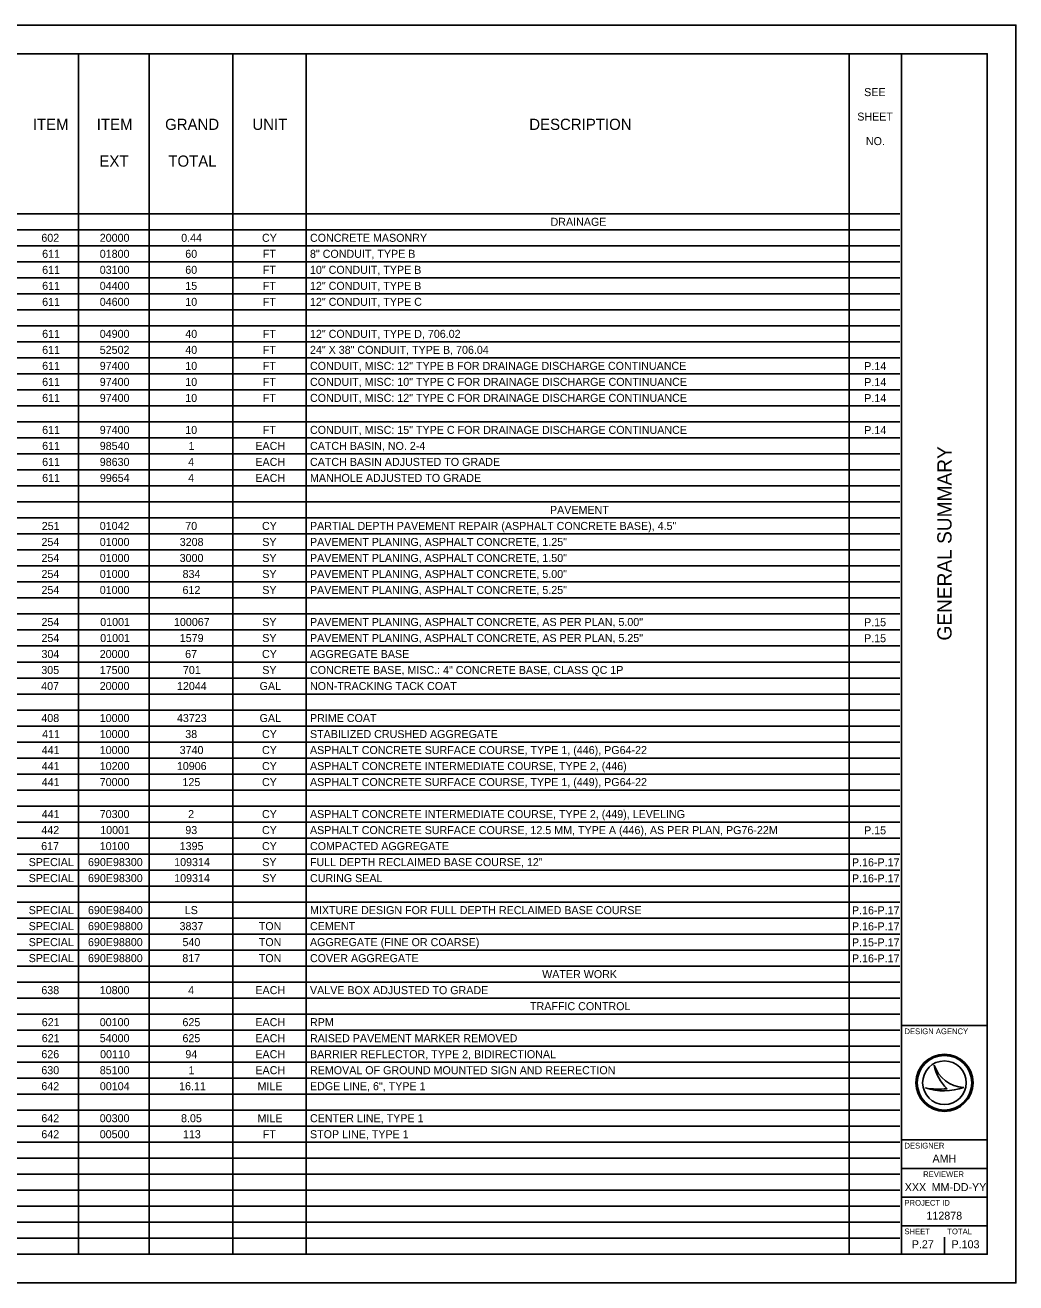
# Model space of a CAD drawing. Extents: x 0 to 34, y 0 to 22.
# Drawn here: x 16.66 to 34, y 0 to 22 of the extents above; entities that cross this region are included whole.
import ezdxf

# ---------------------------------------------------------------- set-up
doc = ezdxf.new("R2010")
doc.units = 0
for name, color, linetype in [('SH_Border', 7, 'Continuous'), ('SH_Cut_Line', 7, 'Continuous'), ('SH_Data', 7, 'Continuous'), ('SH_Text', 7, 'Continuous')]:
    doc.layers.add(name, color=color, linetype=linetype)

msp = doc.modelspace()

# ---------------------------------------------------------------- linework, layer by layer
at = {"layer": 'SH_Border'}
for p, q in [((32, 0.5), (32, 21.5)), ((32, 4.5), (33.5, 4.5)), ((32, 2.5), (33.5, 2.5)), ((32, 2), (33.5, 2)), ((32, 1.5), (33.5, 1.5)), ((32, 1), (33.5, 1))]:
    msp.add_line(p, q, dxfattribs=at)
msp.add_lwpolyline([(1.5, 21.5), (33.5, 21.5), (33.5, 0.5), (1.5, 0.5)], close=True, dxfattribs=at)
at = {"layer": 'SH_Cut_Line'}
msp.add_lwpolyline([(0, 0), (34, 0), (34, 22), (0, 22)], close=True, dxfattribs=at)
at = {"layer": 'SH_Data'}
for p, q in [((32.567, 3.81), (32.567, 3.81)), ((32.417, 3.41), (32.417, 3.41)), ((32.75, 3.5), (32.75, 3.5)), ((33.087, 3.419), (33.087, 3.419)), ((32.375, 0.675), (32.375, 0.675)), ((32.75, 0.5), (32.75, 0.8))]:
    msp.add_line(p, q, dxfattribs=at)
for radius in [0.5, 0.477, 0.477, 0.382]:
    msp.add_circle((32.75, 3.5), radius, dxfattribs=at)
for centre, radius, start, end in [((33.116, 3.998), 0.58, 198.9257, 198.9319), ((33.347, 3.97), 0.796, 191.6379, 191.6421), ((33.116, 3.998), 0.58, 198.9319, 267.1657), ((33.347, 3.97), 0.796, 191.6421, 226.0947), ((32.739, 4.37), 1.013, 251.4576, 290.0832), ((32.648, 4.654), 1.266, 259.4964, 259.4995), ((32.739, 4.37), 1.013, 251.4527, 251.4576), ((32.648, 4.654), 1.266, 259.4995, 276.6672)]:
    msp.add_arc(centre, radius, start, end, dxfattribs=at)
at = {"layer": 'SH_Text'}
for p, q in [((1.5, 21.5), (31.971, 21.5)), ((17.592, 21.5), (17.592, 0.5)), ((18.827, 21.5), (18.827, 0.5)), ((20.293, 21.5), (20.293, 0.5)), ((21.578, 21.5), (21.578, 0.5)), ((31.081, 21.5), (31.081, 0.5)), ((1.5, 18.7), (31.971, 18.7)), ((1.5, 18.42), (31.971, 18.42)), ((1.5, 18.14), (31.971, 18.14)), ((1.5, 17.86), (31.971, 17.86)), ((1.5, 17.58), (31.971, 17.58)), ((1.5, 17.3), (31.971, 17.3)), ((1.5, 17.02), (31.971, 17.02)), ((1.5, 16.74), (31.971, 16.74)), ((1.5, 16.46), (31.971, 16.46)), ((1.5, 16.18), (31.971, 16.18)), ((1.5, 15.9), (31.971, 15.9)), ((1.5, 15.62), (31.971, 15.62)), ((1.5, 15.34), (31.971, 15.34)), ((1.5, 15.06), (31.971, 15.06)), ((1.5, 14.78), (31.971, 14.78)), ((1.5, 14.5), (31.971, 14.5)), ((1.5, 14.22), (31.971, 14.22)), ((1.5, 13.94), (31.971, 13.94)), ((1.5, 13.66), (31.971, 13.66)), ((1.5, 13.38), (31.971, 13.38)), ((1.5, 13.1), (31.971, 13.1)), ((1.5, 12.82), (31.971, 12.82)), ((1.5, 12.54), (31.971, 12.54)), ((1.5, 12.26), (31.971, 12.26)), ((1.5, 11.98), (31.971, 11.98)), ((1.5, 11.7), (31.971, 11.7)), ((1.5, 11.42), (31.971, 11.42)), ((1.5, 11.14), (31.971, 11.14)), ((1.5, 10.86), (31.971, 10.86)), ((1.5, 10.58), (31.971, 10.58)), ((1.5, 10.3), (31.971, 10.3)), ((1.5, 10.02), (31.971, 10.02)), ((1.5, 9.74), (31.971, 9.74)), ((1.5, 9.46), (31.971, 9.46)), ((1.5, 9.18), (31.971, 9.18)), ((1.5, 8.9), (31.971, 8.9)), ((1.5, 8.62), (31.971, 8.62)), ((1.5, 8.34), (31.971, 8.34)), ((1.5, 8.06), (31.971, 8.06)), ((1.5, 7.78), (31.971, 7.78)), ((1.5, 7.5), (31.971, 7.5)), ((1.5, 7.22), (31.971, 7.22)), ((1.5, 6.94), (31.971, 6.94)), ((1.5, 6.66), (31.971, 6.66)), ((1.5, 6.38), (31.971, 6.38)), ((1.5, 6.1), (31.971, 6.1)), ((1.5, 5.82), (31.971, 5.82)), ((1.5, 5.54), (31.971, 5.54)), ((1.5, 5.26), (31.971, 5.26)), ((1.5, 4.98), (31.971, 4.98)), ((1.5, 4.7), (31.971, 4.7)), ((1.5, 4.42), (31.971, 4.42)), ((1.5, 4.14), (31.971, 4.14)), ((1.5, 3.86), (31.971, 3.86)), ((1.5, 3.58), (31.971, 3.58)), ((1.5, 3.3), (31.971, 3.3)), ((1.5, 3.02), (31.971, 3.02)), ((1.5, 2.74), (31.971, 2.74)), ((1.5, 2.46), (31.971, 2.46)), ((1.5, 2.18), (31.971, 2.18)), ((1.5, 1.9), (31.971, 1.9)), ((1.5, 1.62), (31.971, 1.62)), ((1.5, 1.34), (31.971, 1.34)), ((1.5, 1.06), (31.971, 1.06)), ((1.5, 0.78), (31.971, 0.78))]:
    msp.add_line(p, q, dxfattribs=at)

# ---------------------------------------------------------------- texts
at = {"layer": 'SH_Data'}
msp.add_text('GENERAL SUMMARY', height=0.25, rotation=90, dxfattribs=at).set_placement((32.875, 11.235))
for s, height, p in [('DESIGN AGENCY', 0.1, (32.05, 4.35)), ('DESIGNER', 0.1, (32.05, 2.35)), ('AMH', 0.14, (32.541, 2.105)), ('REVIEWER', 0.1, (32.378, 1.85)), ('XXX', 0.14, (32.055, 1.605)), ('MM-DD-YY', 0.14, (32.526, 1.605)), ('PROJECT ID', 0.1, (32.05, 1.35)), ('112878', 0.14, (32.435, 1.105)), ('SHEET', 0.1, (32.05, 0.85)), ('TOTAL', 0.1, (32.8, 0.85)), ('P.27', 0.14, (32.178, 0.605)), ('P.103', 0.14, (32.874, 0.605))]:
    msp.add_text(s, height=height, dxfattribs=at).set_placement(p)
at = {"layer": 'SH_Text'}
for s, height, p in [('SEE', 0.14, (31.345, 20.759)), ('SHEET', 0.14, (31.224, 20.331)), ('ITEM', 0.196, (16.792, 20.167)), ('ITEM', 0.196, (17.912, 20.167)), ('GRAND', 0.196, (19.108, 20.167)), ('UNIT', 0.196, (20.636, 20.167)), ('DESCRIPTION', 0.196, (25.482, 20.167)), ('NO.', 0.14, (31.375, 19.902)), ('EXT', 0.196, (17.958, 19.524)), ('TOTAL', 0.196, (19.164, 19.524)), ('DRAINAGE', 0.14, (25.855, 18.49)), ('602', 0.14, (16.942, 18.21)), ('20000', 0.14, (17.964, 18.21)), ('0.44', 0.14, (19.39, 18.21)), ('CY', 0.14, (20.804, 18.21)), ('CONCRETE MASONRY', 0.14, (21.644, 18.21)), ('611', 0.14, (16.956, 17.93)), ('01800', 0.14, (17.964, 17.93)), ('60', 0.14, (19.461, 17.93)), ('FT', 0.14, (20.819, 17.93)), ('8" CONDUIT, TYPE B', 0.14, (21.644, 17.93)), ('611', 0.14, (16.956, 17.65)), ('03100', 0.14, (17.964, 17.65)), ('60', 0.14, (19.461, 17.65)), ('FT', 0.14, (20.819, 17.65)), ('10" CONDUIT, TYPE B', 0.14, (21.644, 17.65)), ('611', 0.14, (16.956, 17.37)), ('04400', 0.14, (17.964, 17.37)), ('15', 0.14, (19.461, 17.37)), ('FT', 0.14, (20.819, 17.37)), ('12" CONDUIT, TYPE B', 0.14, (21.644, 17.37)), ('611', 0.14, (16.956, 17.09)), ('04600', 0.14, (17.964, 17.09)), ('10', 0.14, (19.461, 17.09)), ('FT', 0.14, (20.819, 17.09)), ('12" CONDUIT, TYPE C', 0.14, (21.644, 17.09)), ('611', 0.14, (16.956, 16.53)), ('04900', 0.14, (17.964, 16.53)), ('40', 0.14, (19.461, 16.53)), ('FT', 0.14, (20.819, 16.53)), ('12" CONDUIT, TYPE D, 706.02', 0.14, (21.644, 16.53)), ('611', 0.14, (16.956, 16.25)), ('52502', 0.14, (17.964, 16.25)), ('40', 0.14, (19.461, 16.25)), ('FT', 0.14, (20.819, 16.25)), ('24" X 38" CONDUIT, TYPE B, 706.04', 0.14, (21.644, 16.25)), ('611', 0.14, (16.956, 15.97)), ('97400', 0.14, (17.964, 15.97)), ('10', 0.14, (19.461, 15.97)), ('FT', 0.14, (20.819, 15.97)), ('CONDUIT, MISC: 12" TYPE B FOR DRAINAGE DISCHARGE CONTINUANCE', 0.14, (21.644, 15.97)), ('P.14', 0.14, (31.346, 15.966)), ('611', 0.14, (16.956, 15.69)), ('97400', 0.14, (17.964, 15.69)), ('10', 0.14, (19.461, 15.69)), ('FT', 0.14, (20.819, 15.69)), ('CONDUIT, MISC: 10" TYPE C FOR DRAINAGE DISCHARGE CONTINUANCE', 0.14, (21.644, 15.69)), ('P.14', 0.14, (31.346, 15.686)), ('611', 0.14, (16.956, 15.41)), ('97400', 0.14, (17.964, 15.41)), ('10', 0.14, (19.461, 15.41)), ('FT', 0.14, (20.819, 15.41)), ('CONDUIT, MISC: 12" TYPE C FOR DRAINAGE DISCHARGE CONTINUANCE', 0.14, (21.644, 15.41)), ('P.14', 0.14, (31.346, 15.406)), ('611', 0.14, (16.956, 14.85)), ('97400', 0.14, (17.964, 14.85)), ('10', 0.14, (19.461, 14.85)), ('FT', 0.14, (20.819, 14.85)), ('CONDUIT, MISC: 15" TYPE C FOR DRAINAGE DISCHARGE CONTINUANCE', 0.14, (21.644, 14.85)), ('P.14', 0.14, (31.346, 14.846)), ('611', 0.14, (16.956, 14.57)), ('98540', 0.14, (17.964, 14.57)), ('1', 0.14, (19.518, 14.57)), ('EACH', 0.14, (20.688, 14.57)), ('CATCH BASIN, NO. 2-4', 0.14, (21.644, 14.57)), ('611', 0.14, (16.956, 14.29)), ('98630', 0.14, (17.964, 14.29)), ('4', 0.14, (19.512, 14.29)), ('EACH', 0.14, (20.688, 14.29)), ('CATCH BASIN ADJUSTED TO GRADE', 0.14, (21.644, 14.29)), ('611', 0.14, (16.956, 14.01)), ('99654', 0.14, (17.966, 14.01)), ('4', 0.14, (19.512, 14.01)), ('EACH', 0.14, (20.688, 14.01)), ('MANHOLE ADJUSTED TO GRADE', 0.14, (21.644, 14.01)), ('PAVEMENT', 0.14, (25.845, 13.45)), ('251', 0.14, (16.949, 13.17)), ('01042', 0.14, (17.964, 13.17)), ('70', 0.14, (19.461, 13.17)), ('CY', 0.14, (20.804, 13.17)), ('PARTIAL DEPTH PAVEMENT REPAIR (ASPHALT CONCRETE BASE), 4.5"', 0.14, (21.644, 13.17)), ('254', 0.14, (16.944, 12.89)), ('01000', 0.14, (17.964, 12.89)), ('3208', 0.14, (19.364, 12.89)), ('SY', 0.14, (20.809, 12.89)), ('PAVEMENT PLANING, ASPHALT CONCRETE, 1.25"', 0.14, (21.644, 12.89)), ('254', 0.14, (16.944, 12.61)), ('01000', 0.14, (17.964, 12.61)), ('3000', 0.14, (19.363, 12.61)), ('SY', 0.14, (20.809, 12.61)), ('PAVEMENT PLANING, ASPHALT CONCRETE, 1.50"', 0.14, (21.644, 12.61)), ('254', 0.14, (16.944, 12.33)), ('01000', 0.14, (17.964, 12.33)), ('834', 0.14, (19.414, 12.33)), ('SY', 0.14, (20.809, 12.33)), ('PAVEMENT PLANING, ASPHALT CONCRETE, 5.00"', 0.14, (21.644, 12.33)), ('254', 0.14, (16.944, 12.05)), ('01000', 0.14, (17.964, 12.05)), ('612', 0.14, (19.413, 12.05)), ('SY', 0.14, (20.809, 12.05)), ('PAVEMENT PLANING, ASPHALT CONCRETE, 5.25"', 0.14, (21.644, 12.05)), ('254', 0.14, (16.944, 11.49)), ('01001', 0.14, (17.972, 11.49)), ('100067', 0.14, (19.263, 11.49)), ('SY', 0.14, (20.809, 11.49)), ('PAVEMENT PLANING, ASPHALT CONCRETE, AS PER PLAN, 5.00"', 0.14, (21.644, 11.49)), ('P.15', 0.14, (31.343, 11.486)), ('254', 0.14, (16.944, 11.21)), ('01001', 0.14, (17.972, 11.21)), ('1579', 0.14, (19.365, 11.21)), ('SY', 0.14, (20.809, 11.21)), ('PAVEMENT PLANING, ASPHALT CONCRETE, AS PER PLAN, 5.25"', 0.14, (21.644, 11.21)), ('P.15', 0.14, (31.343, 11.206)), ('304', 0.14, (16.944, 10.93)), ('20000', 0.14, (17.964, 10.93)), ('67', 0.14, (19.459, 10.93)), ('CY', 0.14, (20.804, 10.93)), ('AGGREGATE BASE', 0.14, (21.644, 10.93)), ('305', 0.14, (16.941, 10.65)), ('17500', 0.14, (17.964, 10.65)), ('701', 0.14, (19.42, 10.65)), ('SY', 0.14, (20.809, 10.65)), ('CONCRETE BASE, MISC.: 4" CONCRETE BASE, CLASS QC 1P', 0.14, (21.644, 10.65)), ('407', 0.14, (16.939, 10.37)), ('20000', 0.14, (17.964, 10.37)), ('12044', 0.14, (19.316, 10.37)), ('GAL', 0.14, (20.762, 10.37)), ('NON-TRACKING TACK COAT', 0.14, (21.644, 10.37)), ('408', 0.14, (16.942, 9.81)), ('10000', 0.14, (17.964, 9.81)), ('43723', 0.14, (19.315, 9.81)), ('GAL', 0.14, (20.762, 9.81)), ('PRIME COAT', 0.14, (21.644, 9.81)), ('411', 0.14, (16.956, 9.53)), ('10000', 0.14, (17.964, 9.53)), ('38', 0.14, (19.461, 9.53)), ('CY', 0.14, (20.804, 9.53)), ('STABILIZED CRUSHED AGGREGATE', 0.14, (21.644, 9.53)), ('441', 0.14, (16.949, 9.25)), ('10000', 0.14, (17.964, 9.25)), ('3740', 0.14, (19.363, 9.25)), ('CY', 0.14, (20.804, 9.25)), ('ASPHALT CONCRETE SURFACE COURSE, TYPE 1, (446), PG64-22', 0.14, (21.644, 9.25)), ('441', 0.14, (16.949, 8.97)), ('10200', 0.14, (17.964, 8.97)), ('10906', 0.14, (19.314, 8.97)), ('CY', 0.14, (20.804, 8.97)), ('ASPHALT CONCRETE INTERMEDIATE COURSE, TYPE 2, (446)', 0.14, (21.644, 8.97)), ('441', 0.14, (16.949, 8.69)), ('70000', 0.14, (17.964, 8.69)), ('125', 0.14, (19.412, 8.69)), ('CY', 0.14, (20.804, 8.69)), ('ASPHALT CONCRETE SURFACE COURSE, TYPE 1, (449), PG64-22', 0.14, (21.644, 8.69)), ('441', 0.14, (16.949, 8.13)), ('70300', 0.14, (17.964, 8.13)), ('2', 0.14, (19.511, 8.13)), ('CY', 0.14, (20.804, 8.13)), ('ASPHALT CONCRETE INTERMEDIATE COURSE, TYPE 2, (449), LEVELING', 0.14, (21.644, 8.13)), ('442', 0.14, (16.942, 7.85)), ('10001', 0.14, (17.972, 7.85)), ('93', 0.14, (19.462, 7.85)), ('CY', 0.14, (20.804, 7.85)), ('ASPHALT CONCRETE SURFACE COURSE, 12.5 MM, TYPE A (446), AS PER PLAN, PG76-22M', 0.14, (21.644, 7.85)), ('P.15', 0.14, (31.343, 7.846)), ('617', 0.14, (16.939, 7.57)), ('10100', 0.14, (17.964, 7.57)), ('1395', 0.14, (19.363, 7.57)), ('CY', 0.14, (20.804, 7.57)), ('COMPACTED AGGREGATE', 0.14, (21.644, 7.57)), ('SPECIAL', 0.14, (16.72, 7.29)), ('690E98300', 0.14, (17.758, 7.29)), ('109314', 0.14, (19.267, 7.29)), ('SY', 0.14, (20.809, 7.29)), ('FULL DEPTH RECLAIMED BASE COURSE, 12"', 0.14, (21.644, 7.29)), ('P.16-P.17', 0.14, (31.131, 7.286)), ('SPECIAL', 0.14, (16.72, 7.01)), ('690E98300', 0.14, (17.758, 7.01)), ('109314', 0.14, (19.267, 7.01)), ('SY', 0.14, (20.809, 7.01)), ('CURING SEAL', 0.14, (21.644, 7.01)), ('P.16-P.17', 0.14, (31.131, 7.006)), ('SPECIAL', 0.14, (16.72, 6.45)), ('690E98400', 0.14, (17.758, 6.45)), ('LS', 0.14, (19.452, 6.45)), ('MIXTURE DESIGN FOR FULL DEPTH RECLAIMED BASE COURSE', 0.14, (21.644, 6.45)), ('P.16-P.17', 0.14, (31.131, 6.446)), ('SPECIAL', 0.14, (16.72, 6.17)), ('690E98800', 0.14, (17.758, 6.17)), ('3837', 0.14, (19.361, 6.17)), ('TON', 0.14, (20.748, 6.17)), ('CEMENT', 0.14, (21.644, 6.17)), ('P.16-P.17', 0.14, (31.131, 6.166)), ('SPECIAL', 0.14, (16.72, 5.89)), ('690E98800', 0.14, (17.758, 5.89)), ('540', 0.14, (19.412, 5.89)), ('TON', 0.14, (20.748, 5.89)), ('AGGREGATE (FINE OR COARSE)', 0.14, (21.644, 5.89)), ('P.15-P.17', 0.14, (31.131, 5.886)), ('SPECIAL', 0.14, (16.72, 5.61)), ('690E98800', 0.14, (17.758, 5.61)), ('817', 0.14, (19.41, 5.61)), ('TON', 0.14, (20.748, 5.61)), ('COVER AGGREGATE', 0.14, (21.644, 5.61)), ('P.16-P.17', 0.14, (31.131, 5.606)), ('WATER WORK', 0.14, (25.708, 5.33)), ('638', 0.14, (16.942, 5.05)), ('10800', 0.14, (17.964, 5.05)), ('4', 0.14, (19.512, 5.05)), ('EACH', 0.14, (20.688, 5.05)), ('VALVE BOX ADJUSTED TO GRADE', 0.14, (21.644, 5.05)), ('TRAFFIC CONTROL', 0.14, (25.496, 4.77)), ('621', 0.14, (16.949, 4.49)), ('00100', 0.14, (17.964, 4.49)), ('625', 0.14, (19.412, 4.49)), ('EACH', 0.14, (20.688, 4.49)), ('RPM', 0.14, (21.644, 4.49)), ('621', 0.14, (16.949, 4.21)), ('54000', 0.14, (17.964, 4.21)), ('625', 0.14, (19.412, 4.21)), ('EACH', 0.14, (20.688, 4.21)), ('RAISED PAVEMENT MARKER REMOVED', 0.14, (21.644, 4.21)), ('626', 0.14, (16.942, 3.93)), ('00110', 0.14, (17.97, 3.93)), ('94', 0.14, (19.463, 3.93)), ('EACH', 0.14, (20.688, 3.93)), ('BARRIER REFLECTOR, TYPE 2, BIDIRECTIONAL', 0.14, (21.644, 3.93)), ('630', 0.14, (16.942, 3.65)), ('85100', 0.14, (17.964, 3.65)), ('1', 0.14, (19.518, 3.65)), ('EACH', 0.14, (20.688, 3.65)), ('REMOVAL OF GROUND MOUNTED SIGN AND REERECTION', 0.14, (21.644, 3.65)), ('642', 0.14, (16.942, 3.37)), ('00104', 0.14, (17.966, 3.37)), ('16.11', 0.14, (19.353, 3.37)), ('MILE', 0.14, (20.726, 3.37)), ('EDGE LINE, 6", TYPE 1', 0.14, (21.644, 3.37)), ('642', 0.14, (16.942, 2.81)), ('00300', 0.14, (17.964, 2.81)), ('8.05', 0.14, (19.387, 2.81)), ('MILE', 0.14, (20.726, 2.81)), ('CENTER LINE, TYPE 1', 0.14, (21.644, 2.81)), ('642', 0.14, (16.942, 2.53)), ('00500', 0.14, (17.964, 2.53)), ('113', 0.14, (19.42, 2.53)), ('FT', 0.14, (20.819, 2.53)), ('STOP LINE, TYPE 1', 0.14, (21.644, 2.53))]:
    msp.add_text(s, height=height, dxfattribs=at).set_placement(p)

doc.saveas('drawing.dxf')
